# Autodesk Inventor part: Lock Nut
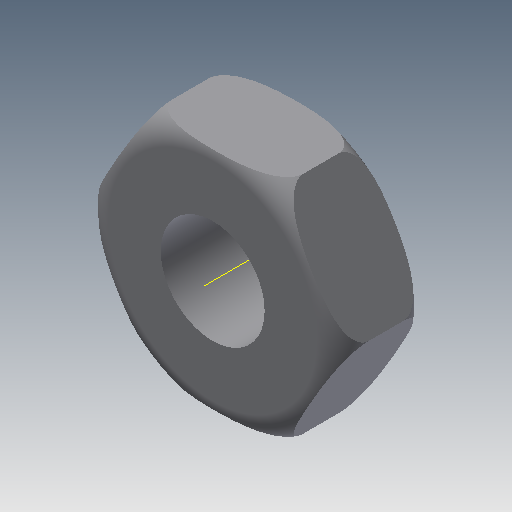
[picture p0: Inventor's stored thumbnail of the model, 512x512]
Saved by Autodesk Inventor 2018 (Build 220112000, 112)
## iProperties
Created: 2009-04
Part Number: Lock Nut
Document SubType Name: Modeling
Designer: Sham
Density: 1 g/cm^3
Material: Generic
Appearance: Default
Author: Sham
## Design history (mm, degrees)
sketch "Sketch1"
  geometry: L1 (7.5, 12.99)-(15, 0); L2 (15, 0)-(7.5, -12.99); L3 (7.5, -12.99)-(-7.5, -12.99); L4 (-7.5, -12.99)-(-15, 0); L5 (-15, 0)-(-7.5, 12.99); L6 (-7.5, 12.99)-(7.5, 12.99); C1 r 6 at (0, 0); 1 further point
  constraints: 12 end point, 1 centre point, 1 coincident, 13 other
  dimensions: "d0" = 30 distance of L1.end L4.end; "d1" = 12 diameter of C1
extrude "Extrusion1" new body sketch "Sketch1" distance "d2" = 10; taper "d3" = 0 deg
sketch "Sketch2"
  geometry: L1 (-12, 0)-(-12, -0.022); L2 (-15, 7)-(-15, 3); L3 (0, -2.87)-(0, 12.87) reference; A1 r 3 centre (-12, 7) between (-12, 10) and (-15, 7); A2 r 3 centre (-12, 3) between (-15, 3) and (-12, 0)
  constraints: 4 end point, 4 point on circle, 2 centre point, 1 tangent
revolve "Revolution1" sketch "Sketch2" stored, may be unused: angle "d7" = 90 deg
body "Solid1"
other parameters: "d6" = 90 deg
